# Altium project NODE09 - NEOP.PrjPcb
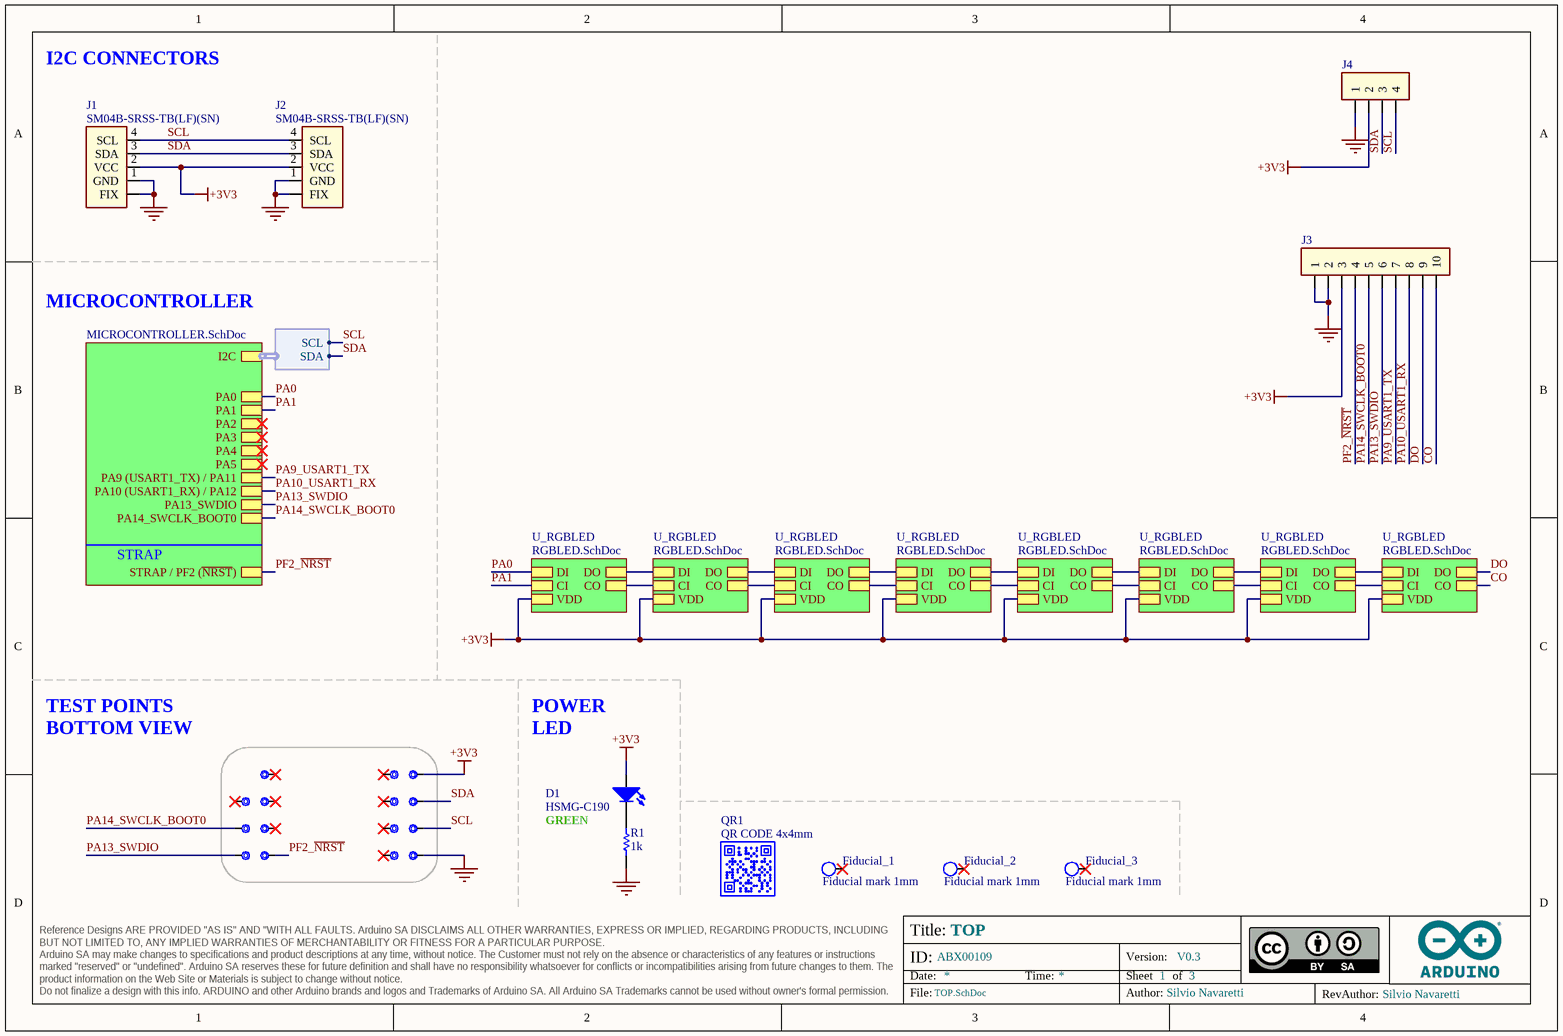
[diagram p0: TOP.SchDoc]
VIA_THROUGH_PAD_MM: 0.6; VIA_THROUGH_HOLE_MM: 0.3; VIA_THROUGH: X; VIA_5_PAD_MM: _; VIA_5_HOLE_MM: _; VIA_5: _; VIA_4_PAD_MM: _; VIA_4_HOLE_MM: _; VIA_4: _; VIA_3_PAD_MM: _; VIA_3_HOLE_MM: _; VIA_3: _; VIA_2_PAD_MM: _; VIA_2_HOLE_MM: _; VIA_2: _; VIA_1_PAD_MM: _; VIA_1_HOLE_MM: _; VIA_1: _; Version: V0.3; TRACK_MIN_WIDTH_OUTER: 0.15mm; TRACK_MIN_WIDTH_INNER: 0.15mm; SKU: ABX00109; PANEL_TABS: _; PANEL_SIZE: 262x221mm; PANEL_SCORING: X; PANEL_REQUESTED: _; PANEL_PROVIDED: X; PANEL_NUMBER_OF_FIGURES: 30; PANEL_NOT_REQUESTED: _; PANEL_MILLING: X; INSULATION_MIN_OUTER: 0.15mm; INSULATION_MIN_INNER: 0.15mm; FINISH_TBD: _; FINISH_TABS: _; FINISH_SOLDERMASK_TOP: X; FINISH_SOLDERMASK_PEELABLE_TOP: _; FINISH_SOLDERMASK_PEELABLE_COLOR: _; FINISH_SOLDERMASK_PEELABLE_BOTTOM: _; FINISH_SOLDERMASK_COLOR: BLUE; FINISH_SOLDERMASK_BOTTOM: X; FINISH_SN/PB: _; FINISH_SILK_TOP: X; FINISH_SILK_COLOR: WHITE; FINISH_SILK_BOTTOM: X; FINISH_NI/AU: _; FINISH_HAL_LF: X; FINISH_HAL: _; FINISH_ENIG: _; FINISH_EDGE_PLATING: _; FINISH_ADJUSTMENTS: _; DRILLS_SOLDER_FILLING: X; DRILLS_SLOT: _; DRILLS_RESIN_FILLING: _; DRILLS_PRESSFIT: _; DRILLS_LASER: _; DRILLS_FULL: X; DRILLS_COPPER_FILLING: _; DRILLS_BURIED: _; DRILLS_BLIND: _; BOARD_INFO_THICKNESS: 1.6mm; BOARD_INFO_TBD: _; BOARD_INFO_RIGID/FLEX: _; BOARD_INFO_RIGID: X; BOARD_INFO_POLYMIDE: _; BOARD_INFO_PCB_SImm: 41.00x25.36mm; BOARD_INFO_NUMBER_OF_LAYERS: 2; BOARD_INFO_IPC_NA: _; BOARD_INFO_IPC3: _; BOARD_INFO_IPC2: X; BOARD_INFO_IPC1: _; BOARD_INFO_FR4_HTG: _; BOARD_INFO_FR4: X; BOARD_INFO_FLEX: _; BOARD_INFO_Er: _; BOARD_INFO_AUTHOR_REV: Silvio Navaretti; BOARD_INFO_AUTHOR: Silvio Navaretti; BOARD_CODENAME: NODE09; ASSEMBLY_THT: _; ASSEMBLY_SMD: X; ASSEMBLY_PRESSFIT: _; ASSEMBLY_BGA: _
3 sheets, 60 parts. Net scope: hierarchical (ports join the sheet entries above them; power ports are global).
Board files: PCB.PcbDoc, PANEL.PcbDoc
Sheets:
  TOP.SchDoc
    U_RGBLED = RGBLED.SchDoc
    U_RGBLED = RGBLED.SchDoc
    U_RGBLED = RGBLED.SchDoc
    U_RGBLED = RGBLED.SchDoc
    U_RGBLED = RGBLED.SchDoc
    U_RGBLED = RGBLED.SchDoc
    U_RGBLED = RGBLED.SchDoc
    U_RGBLED = RGBLED.SchDoc
    U_MICROCONTROLLER = MICROCONTROLLER.SchDoc

## Sheet TOP.SchDoc: TOP
size A4; Revision: V0.3; SheetNumber: 1; SheetTotal: 3

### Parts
3V3  Test point 1.00mm  [TP-1.00MM]  (value not drawn)  (no BOM)
D1  HSMG-C190  [LEDC1608X80N-AK]
Fiducial_1  Fiducial mark 1mm  [Fiducial mark 1mm-Footprint-1]  (no BOM)
Fiducial_2  Fiducial mark 1mm  [Fiducial mark 1mm-Footprint-1]  (no BOM)
Fiducial_3  Fiducial mark 1mm  [Fiducial mark 1mm-Footprint-1]  (no BOM)
GND  Test point 1.00mm  [TP-1.00MM]  (value not drawn)  (no BOM)
J1  SM04B-SRSS-TB(LF)(SN)  [SM04B-SRSS-TB(LF)(SN)-Footprint-1]
J2  SM04B-SRSS-TB(LF)(SN)  [SM04B-SRSS-TB(LF)(SN)-Footprint-1]
J3  HEADER TH 2.54mm VERT. 1x010POS  [PIN HEADER 2.54mm VERT. 1x10POS]  (value not drawn)  (no BOM)
J4  HEADER TH 2.54mm VERT. 1x004POS  [PIN HEADER 2.54mm VERT. 1x4POS-Footprint-1]  (value not drawn)  (no BOM)
NRST  Test point 1.00mm  [TP-1.00MM]  (value not drawn)  (no BOM)
PA6  Test point 1.00mm  [TP-1.00MM]  (value not drawn)  (no BOM)
PA7  Test point 1.00mm  [TP-1.00MM]  (value not drawn)  (no BOM)
PC14  Test point 1.00mm  [TP-1.00MM]  (value not drawn)  (no BOM)
PC15  Test point 1.00mm  [TP-1.00MM]  (value not drawn)  (no BOM)
QR1  QR CODE 4x4mm  [QR CODE 4x4mm]  (no BOM)
R1  value 1k  [RES-0402]  (hidden comment: CRCW04021K00FKEDC)
SCL  Test point 1.00mm  [TP-1.00MM]  (value not drawn)  (no BOM)
SDA  Test point 1.00mm  [TP-1.00MM]  (value not drawn)  (no BOM)
SWCLK  Test point 1.00mm  [TP-1.00MM]  (value not drawn)  (no BOM)
SWDIO  Test point 1.00mm  [TP-1.00MM]  (value not drawn)  (no BOM)
TP9  Test point 1.00mm  [TP-1.00MM]  (value not drawn)  (no BOM)
TP10  Test point 1.00mm  [TP-1.00MM]  (value not drawn)  (no BOM)
TP11  Test point 1.00mm  [TP-1.00MM]  (value not drawn)  (no BOM)
TP12  Test point 1.00mm  [TP-1.00MM]  (value not drawn)  (no BOM)

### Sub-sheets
U_MICROCONTROLLER = MICROCONTROLLER.SchDoc: I2C (harness I2C), PA0, PA1, PA2, PA3, PA4, PA5, PA13_SWDIO, PA14_SWCLK_BOOT0, PA9 (USART1_TX) / PA11, PA10 (USART1_RX) / PA12, STRAP / PF2 (~{NRST})
U_RGBLED = RGBLED.SchDoc: DI, CI, DO, CO, VDD
U_RGBLED = RGBLED.SchDoc: DI, CI, DO, CO, VDD
U_RGBLED = RGBLED.SchDoc: DI, CI, DO, CO, VDD
U_RGBLED = RGBLED.SchDoc: DI, CI, DO, CO, VDD
U_RGBLED = RGBLED.SchDoc: DI, CI, DO, CO, VDD
U_RGBLED = RGBLED.SchDoc: DI, CI, DO, CO, VDD
U_RGBLED = RGBLED.SchDoc: DI, CI, DO, CO, VDD
U_RGBLED = RGBLED.SchDoc: DI, CI, DO, CO, VDD

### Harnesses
I2C: SDA, SCL

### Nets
+3V3: 3V3.X D1.A J1.2(VCC) J2.2(VCC) J3.3 J4.2 ; sheet U_RGBLED/VDD, sheet U_RGBLED/VDD, sheet U_RGBLED/VDD, sheet U_RGBLED/VDD, sheet U_RGBLED/VDD, sheet U_RGBLED/VDD, sheet U_RGBLED/VDD, sheet U_RGBLED/VDD
GND: GND.X J1.1(GND) J1.FIX J2.1(GND) J2.FIX J3.1 J3.2 J4.1 R1.1
CO: J3.10 ; sheet U_RGBLED/CO
DO: J3.9 ; sheet U_RGBLED/DO
PA0: sheet U_RGBLED/DI, sheet U_MICROCONTROLLER/PA0
PA1: sheet U_RGBLED/CI, sheet U_MICROCONTROLLER/PA1
PA9_USART1_TX: J3.7 ; sheet U_MICROCONTROLLER/PA9 (USART1_TX) / PA11
PA10_USART1_RX: J3.8 ; sheet U_MICROCONTROLLER/PA10 (USART1_RX) / PA12
PA13_SWDIO: J3.6 SWCLK.X ; sheet U_MICROCONTROLLER/PA13_SWDIO
PA14_SWCLK_BOOT0: J3.5 SWDIO.X ; sheet U_MICROCONTROLLER/PA14_SWCLK_BOOT0
PF2_~{NRST}: J3.4 NRST.X ; sheet U_MICROCONTROLLER/STRAP / PF2 (~{NRST})
SCL: J1.4(SCL) J2.4(SCL) J4.4 SCL.X ; sheet U_MICROCONTROLLER/I2C.SCL
SDA: J1.3(SDA) J2.3(SDA) J4.3 SDA.X ; sheet U_MICROCONTROLLER/I2C.SDA
NetD1_C: D1.C R1.2
NetDL1_1_5: sheet U_RGBLED/CO, sheet U_RGBLED/CI
NetDL1_1_6: sheet U_RGBLED/DO, sheet U_RGBLED/DI
NetDL1_2_5: sheet U_RGBLED/CO, sheet U_RGBLED/CI
NetDL1_2_6: sheet U_RGBLED/DO, sheet U_RGBLED/DI
NetDL1_3_5: sheet U_RGBLED/CO, sheet U_RGBLED/CI
NetDL1_3_6: sheet U_RGBLED/DO, sheet U_RGBLED/DI
NetDL1_4_5: sheet U_RGBLED/CO, sheet U_RGBLED/CI
NetDL1_4_6: sheet U_RGBLED/DO, sheet U_RGBLED/DI
NetDL1_5_5: sheet U_RGBLED/CO, sheet U_RGBLED/CI
NetDL1_5_6: sheet U_RGBLED/DO, sheet U_RGBLED/DI
NetDL1_6_5: sheet U_RGBLED/CO, sheet U_RGBLED/CI
NetDL1_6_6: sheet U_RGBLED/DO, sheet U_RGBLED/DI
NetDL1_7_5: sheet U_RGBLED/CO, sheet U_RGBLED/CI
NetDL1_7_6: sheet U_RGBLED/DO, sheet U_RGBLED/DI

Not connected (* = marked no-connect by the designer): Fiducial_1 1*; Fiducial_2 1*; Fiducial_3 1*; PA6 X*; PA7 X*; PC14 X*; PC15 X*; TP9 X*; TP10 X*; TP11 X*; TP12 X*

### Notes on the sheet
- I2C CONNECTORS
- MICROCONTROLLER
- STRAP
- TEST POINTS BOTTOM VIEW
- (near D1) POWER LED
- GREEN

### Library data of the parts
3V3 GND NRST PA6 PA7 PC14 PC15 SCL SDA SWCLK SWDIO TP9-TP12 = UT0013-A.6: Manufacturer: This is not a component
D1 = L0009-A.5: LED SMD 0603 GREEN/568 15mcd 120^; Manufacturer: Broadcom; Code Arduino: 2204
Fiducial_1-Fiducial_3 = UT0023-A.7: Fiducial mark 1mm clearance 2mm
J1 J2 = J0005-A.2: CONN JST 4POS SIDE 1MM TIN QWIIC; Code Arduino: J0005
J3 = J0169-A.8: Code Arduino: J0169
J4 = J0162-A.5: Code Arduino: J0162
QR1 = QR-0001-A.2: QR CODE 4x4mm on layer 34 (This is not a component); Code Arduino: QRCODE_4x4mm
R1 = R0007-A.24: RES CHIP 0402 1k 1% 1/16W; Manufacturer: Vishay; Code Arduino: 0140; Power: 62.5mW; Temperature coefficient: 100ppm

## Sheet RGBLED.SchDoc
size A4; SheetNumber: 3; SheetTotal: 2
Used 8 times, as channels U_RGBLED, U_RGBLED, U_RGBLED, U_RGBLED, U_RGBLED, U_RGBLED, U_RGBLED, U_RGBLED. Parts and nets are listed once, with the designators drawn on the sheet.
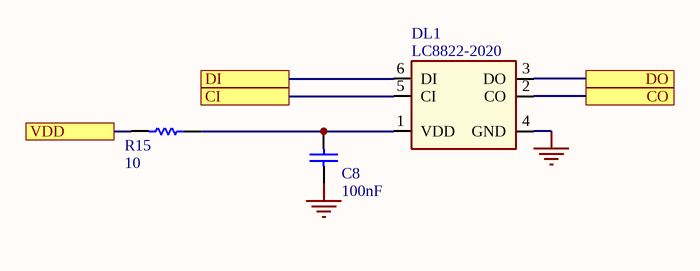
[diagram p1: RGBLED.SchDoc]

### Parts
C8  value 100nF  [CAP-0402]  (hidden comment: 0402B104K160CT)
DL1  LC8822-2020  [APA102-2020]
R15  value 10  [RES-0603]  (hidden comment: CRCW060310R0FKEAC)

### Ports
CI, CO, DI, DO, VDD

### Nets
GND: C8.2 DL1.4(GND)
CI: DL1.5(CI) ; port CI
CO: DL1.2(CO) ; port CO
DI: DL1.6(DI) ; port DI
DO: DL1.3(DO) ; port DO
VDD: R15.2 ; port VDD
NetC8_1: C8.1 DL1.1(VDD) R15.1

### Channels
U_RGBLED: designators end in _8; ports CI=PA1 CO=NetDL1_7_5 DI=PA0 DO=NetDL1_7_6 VDD=+3V3
U_RGBLED: designators end in _7; ports CI=NetDL1_7_5 CO=NetDL1_6_5 DI=NetDL1_7_6 DO=NetDL1_6_6 VDD=+3V3
U_RGBLED: designators end in _6; ports CI=NetDL1_6_5 CO=NetDL1_5_5 DI=NetDL1_6_6 DO=NetDL1_5_6 VDD=+3V3
U_RGBLED: designators end in _5; ports CI=NetDL1_5_5 CO=NetDL1_4_5 DI=NetDL1_5_6 DO=NetDL1_4_6 VDD=+3V3
U_RGBLED: designators end in _4; ports CI=NetDL1_4_5 CO=NetDL1_3_5 DI=NetDL1_4_6 DO=NetDL1_3_6 VDD=+3V3
U_RGBLED: designators end in _3; ports CI=NetDL1_3_5 CO=NetDL1_2_5 DI=NetDL1_3_6 DO=NetDL1_2_6 VDD=+3V3
U_RGBLED: designators end in _2; ports CI=NetDL1_2_5 CO=NetDL1_1_5 DI=NetDL1_2_6 DO=NetDL1_1_6 VDD=+3V3
U_RGBLED: designators end in _1; ports CI=NetDL1_1_5 CO=CO DI=NetDL1_1_6 DO=DO VDD=+3V3

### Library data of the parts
C8 = C0012-A.15: CAP CHIP 0402 100nF 10% 16V X7R; Manufacturer: Walsin; Code Arduino: 0132
DL1 = L0003-A.11: LED RGB DATA + CLOCK 2020 2x2x.0.7mm; Manufacturer: Shenzhen LED Color Opto Electronic CO.,LTD.; Code Arduino: A5307
R15 = R0188-A.20: RES CHIP 0603 10R 1% 1/10W; Manufacturer: Vishay; Temperature coefficient: 100ppm; Code Arduino: R0188; Power: 100mW

## Sheet MICROCONTROLLER.SchDoc
size A4; SheetNumber: 2; SheetTotal: 3
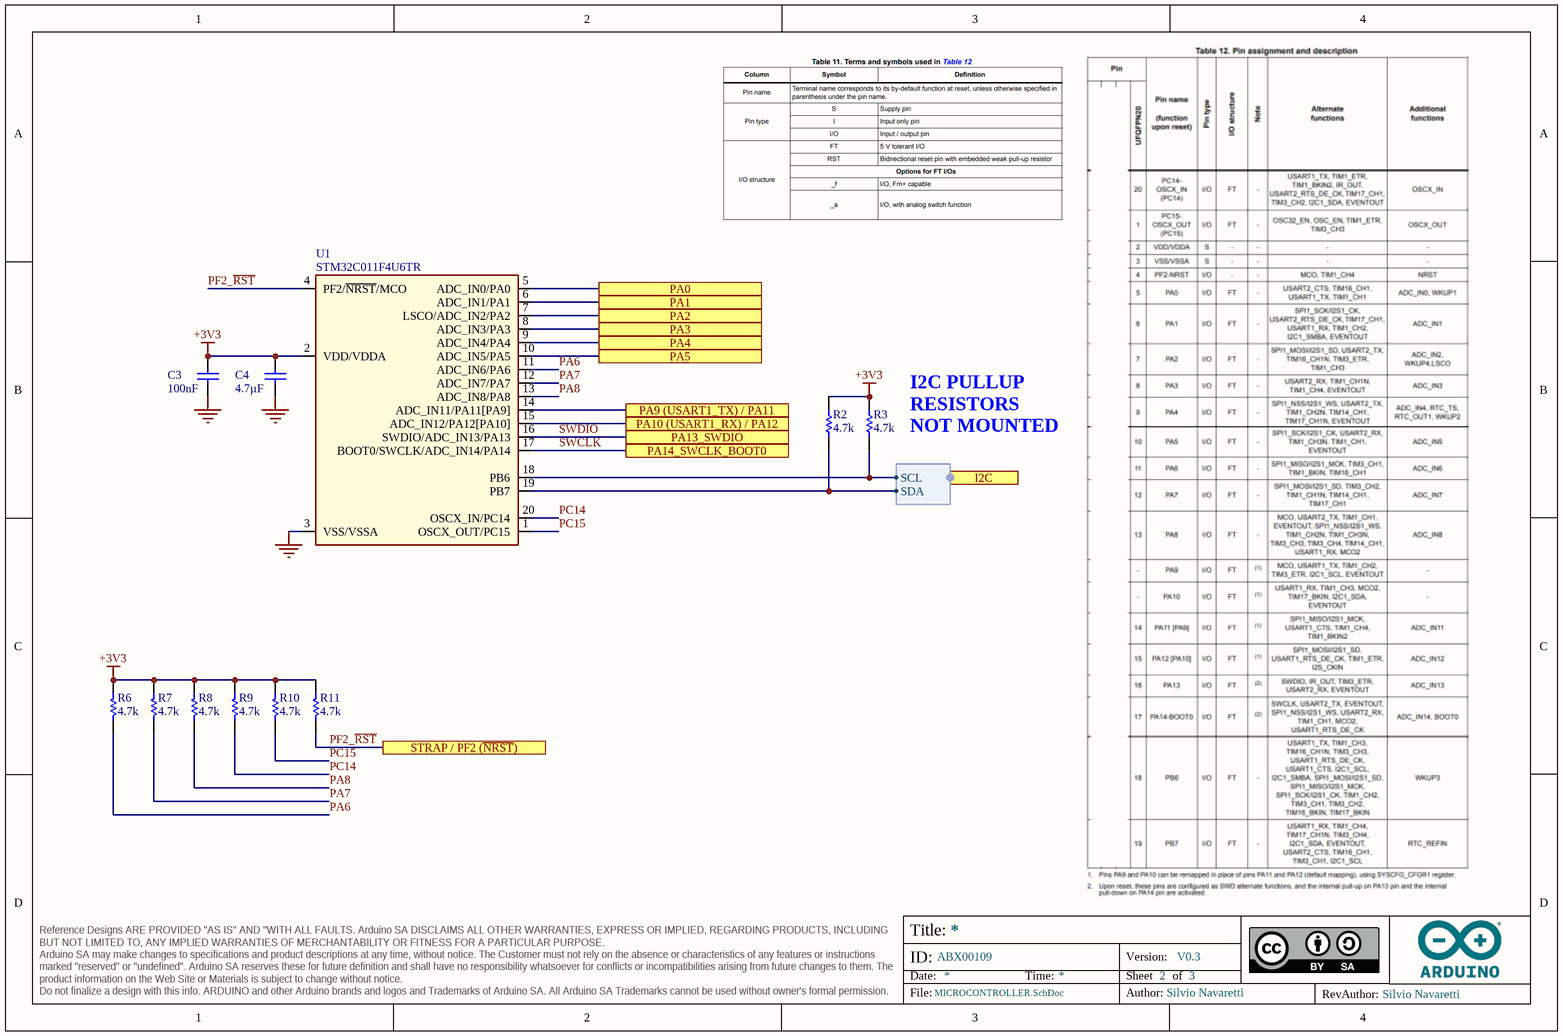
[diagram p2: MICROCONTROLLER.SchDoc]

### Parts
C3  value 100nF  [CAP-0402]  (hidden comment: 0402B104K160CT)
C4  value 4.7µF  [CAP-0603]  (hidden comment: GRM188R61C475KAAJD)
R2  value 4.7k  [RES-0402]  (hidden comment: RC0402FR-074K7L)
R3  value 4.7k  [RES-0402]  (hidden comment: RC0402FR-074K7L)
R6  value 4.7k  [RES-0402]  (hidden comment: RC0402FR-074K7L)
R7  value 4.7k  [RES-0402]  (hidden comment: RC0402FR-074K7L)
R8  value 4.7k  [RES-0402]  (hidden comment: RC0402FR-074K7L)
R9  value 4.7k  [RES-0402]  (hidden comment: RC0402FR-074K7L)
R10  value 4.7k  [RES-0402]  (hidden comment: RC0402FR-074K7L)
R11  value 4.7k  [RES-0402]  (hidden comment: RC0402FR-074K7L)
U1  STM32C011F4U6TR  [UFQFPN20]

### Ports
I2C (harness I2C), PA0, PA1, PA2, PA3, PA4, PA5, PA9 (USART1_TX) / PA11, PA10 (USART1_RX) / PA12, PA13_SWDIO, PA14_SWCLK_BOOT0, STRAP / PF2 (~{NRST})

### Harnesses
I2C: SDA, SCL

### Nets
+3V3: C3.1 C4.2 R2.2 R3.2 R6.1 R7.1 R8.1 R9.1 R10.1 R11.1 U1.2(VDD/VDDA)
GND: C3.2 C4.1 U1.3(VSS/VSSA)
PA0: U1.5(ADC_IN0/PA0) ; port PA0
PA1: U1.6(ADC_IN1/PA1) ; port PA1
PA6: R6.2 U1.11(ADC_IN6/PA6)  [project net PA6_2]
PA7: R7.2 U1.12(ADC_IN7/PA7)  [project net PA7_2]
PA8: R8.2 U1.13(ADC_IN8/PA8)  [project net PA8_2]
PA9_USART1_TX: U1.14(ADC_IN11/PA11[PA9]) ; port PA9 (USART1_TX) / PA11
PA10_USART1_RX: U1.15(ADC_IN12/PA12[PA10]) ; port PA10 (USART1_RX) / PA12
PC14: R9.2 U1.20(OSCX_IN/PC14)  [project net PC14_2]
PC15: R10.2 U1.1(OSCX_OUT/PC15)  [project net PC15_2]
PF2_~{RST}: R11.2 U1.4(PF2/~{NRST}/MCO) ; port STRAP / PF2 (~{NRST})  [project net PF2_~{NRST}]
SCL: R3.1 U1.18(PB6) ; port I2C.SCL
SDA: R2.1 U1.19(PB7) ; port I2C.SDA
SWCLK: U1.17(BOOT0/SWCLK/ADC_IN14/PA14) ; port PA14_SWCLK_BOOT0  [project net PA14_SWCLK_BOOT0]
SWDIO: U1.16(SWDIO/ADC_IN13/PA13) ; port PA13_SWDIO  [project net PA13_SWDIO]
NetU1_7: U1.7(LSCO/ADC_IN2/PA2) ; port PA2
NetU1_8: U1.8(ADC_IN3/PA3) ; port PA3
NetU1_9: U1.9(ADC_IN4/PA4) ; port PA4
NetU1_10: U1.10(ADC_IN5/PA5) ; port PA5

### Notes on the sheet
- (near R3) I2C PULLUP RESISTORS NOT MOUNTED

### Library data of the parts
C3 = C0012-A.15: as C8 on sheet RGBLED
C4 = C0054-A.16: CAP CHIP 0603 4.7uF 10% 16V X5R; Manufacturer: Murata; Code Arduino: A5072
R2 R3 = R0013-A.24: RES CHIP 0402 4k7 1% 1/16W; Manufacturer: YAGEO; Code Arduino: 2196; Power: 62.5mW; Temperature coefficient: 200ppm
R6-R11 = R0013-A.24: RES CHIP 0402 4k7 1% 1/16W; Manufacturer: YAGEO; Power: 62.5mW; Code Arduino: 2196; Temperature coefficient: 200ppm
U1 = U0363-A.3: IC Cortex M0, 32b MCU, 32KB Flash, 6KB RAM, VDD 2-3.6V, -40°C to 85°C, QFN20 3x3mm; Manufacturer: ST Microelectronics; Code Arduino: U0363

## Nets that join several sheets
+3V3: TOP (6 pins), U_RGBLED (R15_8.2), U_RGBLED (R15_7.2), U_RGBLED (R15_6.2), U_RGBLED (R15_5.2), U_RGBLED (R15_4.2), U_RGBLED (R15_3.2), U_RGBLED (R15_2.2), U_RGBLED (R15_1.2), MICROCONTROLLER (11 pins)
GND: TOP (9 pins), U_RGBLED (C8_8.2 DL1_8.4), U_RGBLED (C8_7.2 DL1_7.4), U_RGBLED (C8_6.2 DL1_6.4), U_RGBLED (C8_5.2 DL1_5.4), U_RGBLED (C8_4.2 DL1_4.4), U_RGBLED (C8_3.2 DL1_3.4), U_RGBLED (C8_2.2 DL1_2.4), U_RGBLED (C8_1.2 DL1_1.4), MICROCONTROLLER (C3.2 C4.1 U1.3)
CO: TOP (J3.10), U_RGBLED (DL1_1.2)
DO: TOP (J3.9), U_RGBLED (DL1_1.3)
NetDL1_1_5: U_RGBLED (DL1_2.2), U_RGBLED (DL1_1.5)
NetDL1_1_6: U_RGBLED (DL1_2.3), U_RGBLED (DL1_1.6)
NetDL1_2_5: U_RGBLED (DL1_3.2), U_RGBLED (DL1_2.5)
NetDL1_2_6: U_RGBLED (DL1_3.3), U_RGBLED (DL1_2.6)
NetDL1_3_5: U_RGBLED (DL1_4.2), U_RGBLED (DL1_3.5)
NetDL1_3_6: U_RGBLED (DL1_4.3), U_RGBLED (DL1_3.6)
NetDL1_4_5: U_RGBLED (DL1_5.2), U_RGBLED (DL1_4.5)
NetDL1_4_6: U_RGBLED (DL1_5.3), U_RGBLED (DL1_4.6)
NetDL1_5_5: U_RGBLED (DL1_6.2), U_RGBLED (DL1_5.5)
NetDL1_5_6: U_RGBLED (DL1_6.3), U_RGBLED (DL1_5.6)
NetDL1_6_5: U_RGBLED (DL1_7.2), U_RGBLED (DL1_6.5)
NetDL1_6_6: U_RGBLED (DL1_7.3), U_RGBLED (DL1_6.6)
NetDL1_7_5: U_RGBLED (DL1_8.2), U_RGBLED (DL1_7.5)
NetDL1_7_6: U_RGBLED (DL1_8.3), U_RGBLED (DL1_7.6)
PA0: U_RGBLED (DL1_8.6), MICROCONTROLLER (U1.5)
PA1: U_RGBLED (DL1_8.5), MICROCONTROLLER (U1.6)
PA9_USART1_TX: TOP (J3.7), MICROCONTROLLER (U1.14)
PA10_USART1_RX: TOP (J3.8), MICROCONTROLLER (U1.15)
PA13_SWDIO: TOP (J3.6 SWCLK.X), MICROCONTROLLER (U1.16)
PA14_SWCLK_BOOT0: TOP (J3.5 SWDIO.X), MICROCONTROLLER (U1.17)
PF2_~{NRST}: TOP (J3.4 NRST.X), MICROCONTROLLER (R11.2 U1.4)
SCL: TOP (J1.4 J2.4 J4.4 SCL.X), MICROCONTROLLER (R3.1 U1.18)
SDA: TOP (J1.3 J2.3 J4.3 SDA.X), MICROCONTROLLER (R2.1 U1.19)

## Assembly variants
ABX00109: not fitted R2 R3 R8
